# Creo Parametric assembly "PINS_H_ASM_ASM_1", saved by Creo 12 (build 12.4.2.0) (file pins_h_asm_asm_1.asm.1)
Units: Custom; MM, KILOGRAM, SECS

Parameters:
  PTC_WM_ITERATION = "0"
  PTC_WM_VERSION = "-.0"
  PTC_WM_LIFECYCLE_STATE = "In Work"
  PTC_WM_LIFECYCLE = "MO_CADDocument"
  PTC_WM_CREATED_BY = "Maximilian Roepper (Z0017RMS: MO)"
  PTC_WM_CREATED_ON = "18-Sep-26 11:36:42 AM"
  PTC_WM_MODIFIED_BY = "Maximilian Roepper (Z0017RMS: MO)"
  PTC_WM_MODIFIED_ON = "18-Sep-26 11:36:46 AM"
  PDMLINKNUMBER = "PDM000071455299"
  PTC_WM_NUMBER = "PDM000071455299"

Other parameters: WEIGHT, WEIGHT_FACTOR, WEIGHT_ADD, MC_ERRORS, SUPPLIER

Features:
  1. coordinate system
  2. imported feature
  3. component "PIN_001_PRT_1"
  4. component "PIN_002_PRT_1"
  5. component "PIN_003_PRT_1"
  6. component "PIN_004_PRT_1"
  7. component "PIN_005_PRT_1"
  8. component "PIN_006_PRT_1"
  9. component "PIN_007_PRT_1"
  10. component "PIN_008_PRT_1"
  11. component "PIN_009_PRT_1"
  12. component "PIN_010_PRT_1"

Other named items: DRW_VIEW_ORG, ROUGH-GROB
